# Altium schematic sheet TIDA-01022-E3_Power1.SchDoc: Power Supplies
size 431 x 279 mm; Date: Not shown in title block; ApprovedBy: Not shown in title block; CheckedBy: Not shown in title block; Author: Not shown in title block; CompanyName: Not shown in title block; DrawnBy: Avinash N; Engineer: Not shown in title block; Organization: Not shown in title block; Address1: Not shown in title block; Address2: Not shown in title block; Address3: Not shown in title block; Address4: Not shown in title block; DocumentNumber: 1; Revision: Use project parameter SCH_Rev; SheetNumber: 21; SheetTotal: 26; PageSetup: Record=PageOptions¦CenterHorizontal=True¦CenterVertical=True¦PrintScale=1.00¦XCorrection=1.00¦YCorrection=1.00¦PrintKind=0¦BorderSize=5000000¦LeftOffset=0¦BottomOffset=0¦Orientation=2¦PaperLength=1000¦PaperWidth=1000¦Scale=100¦PaperSource=15¦PrintQuality=600¦MediaType=1¦DitherType=10¦PaperKind=Letter¦PrintScaleMode=1
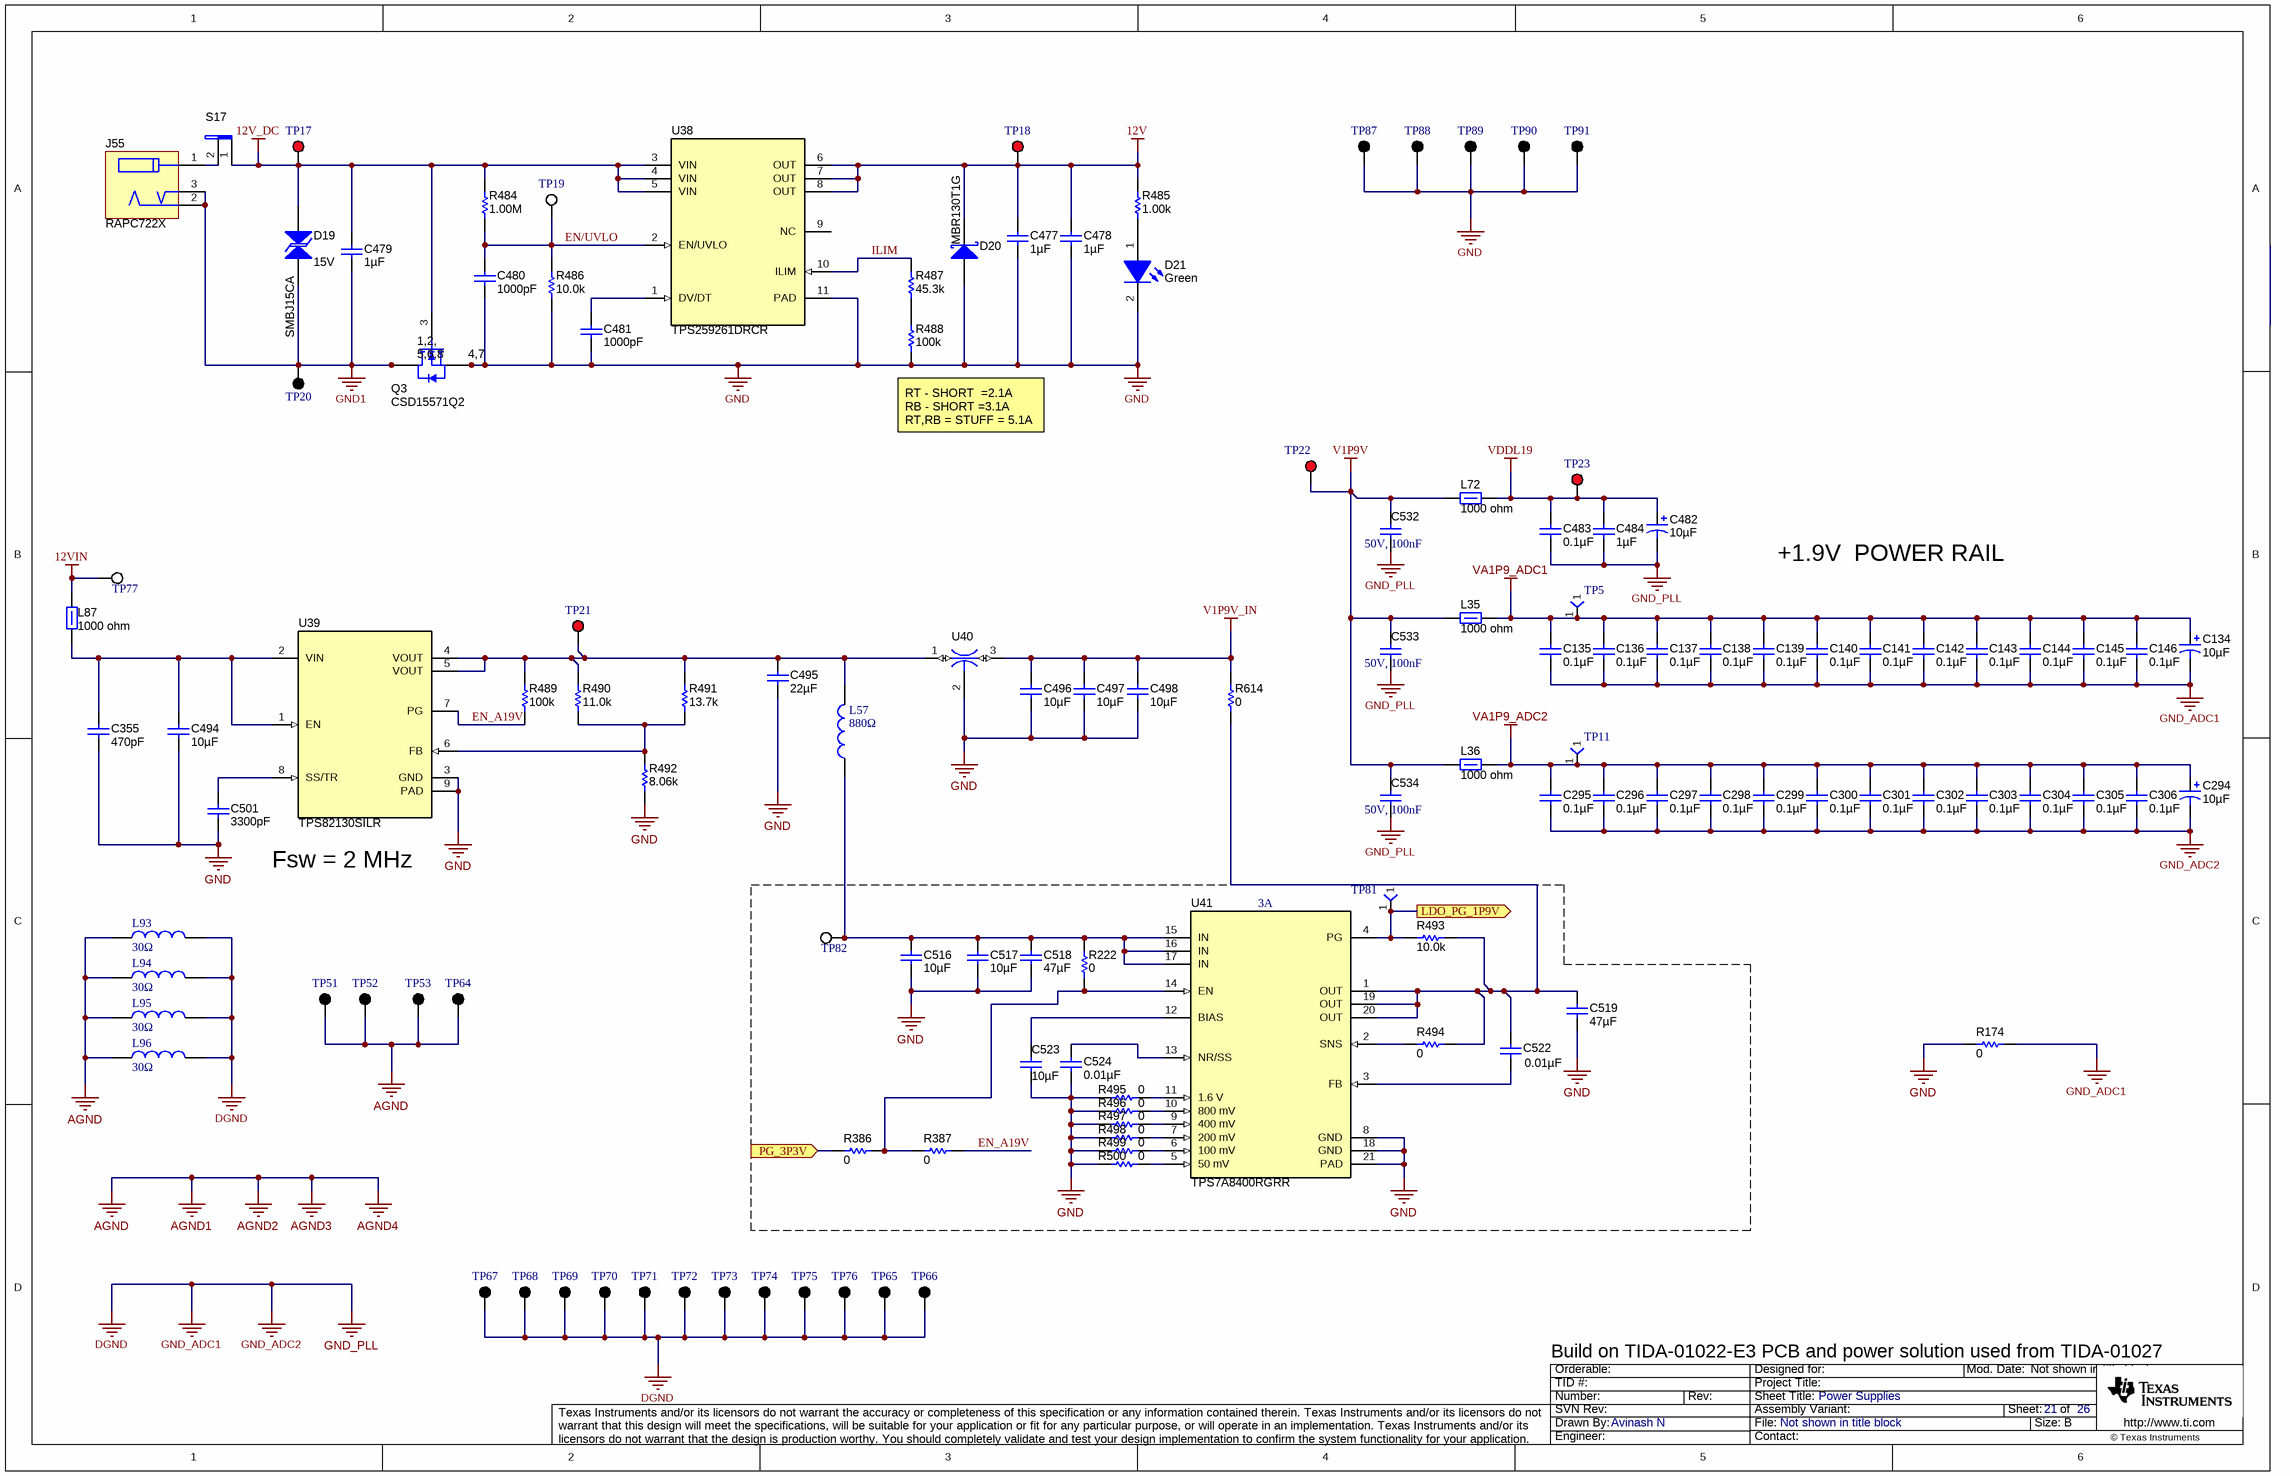
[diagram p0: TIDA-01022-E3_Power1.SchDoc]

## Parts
C134  ValueDisplayed: 10µF  [3528-21]  (hidden comment: 293D106X0010B2TE3)
C135  ValueDisplayed: 0.1µF  [0201]  (hidden comment: GRM033C71A104KE14D)
C136  ValueDisplayed: 0.1µF  [0201]  (hidden comment: GRM033C71A104KE14D)
C137  ValueDisplayed: 0.1µF  [0201]  (hidden comment: GRM033C71A104KE14D)
C138  ValueDisplayed: 0.1µF  [0201]  (hidden comment: GRM033C71A104KE14D)
C139  ValueDisplayed: 0.1µF  [0201]  (hidden comment: GRM033C71A104KE14D)
C140  ValueDisplayed: 0.1µF  [0201]  (hidden comment: GRM033C71A104KE14D)
C141  ValueDisplayed: 0.1µF  [0201]  (hidden comment: GRM033C71A104KE14D)
C142  ValueDisplayed: 0.1µF  [0201]  (hidden comment: GRM033C71A104KE14D)
C143  ValueDisplayed: 0.1µF  [0201]  (hidden comment: GRM033C71A104KE14D)
C144  ValueDisplayed: 0.1µF  [0201]  (hidden comment: GRM033C71A104KE14D)
C145  ValueDisplayed: 0.1µF  [0201]  (hidden comment: GRM033C71A104KE14D)
C146  ValueDisplayed: 0.1µF  [0201]  (hidden comment: GRM033C71A104KE14D)
C294  ValueDisplayed: 10µF  [3528-21]  (hidden comment: 293D106X0010B2TE3)
C295  ValueDisplayed: 0.1µF  [0201]  (hidden comment: GRM033C71A104KE14D)
C296  ValueDisplayed: 0.1µF  [0201]  (hidden comment: GRM033C71A104KE14D)
C297  ValueDisplayed: 0.1µF  [0201]  (hidden comment: GRM033C71A104KE14D)
C298  ValueDisplayed: 0.1µF  [0201]  (hidden comment: GRM033C71A104KE14D)
C299  ValueDisplayed: 0.1µF  [0201]  (hidden comment: GRM033C71A104KE14D)
C300  ValueDisplayed: 0.1µF  [0201]  (hidden comment: GRM033C71A104KE14D)
C301  ValueDisplayed: 0.1µF  [0201]  (hidden comment: GRM033C71A104KE14D)
C302  ValueDisplayed: 0.1µF  [0201]  (hidden comment: GRM033C71A104KE14D)
C303  ValueDisplayed: 0.1µF  [0201]  (hidden comment: GRM033C71A104KE14D)
C304  ValueDisplayed: 0.1µF  [0201]  (hidden comment: GRM033C71A104KE14D)
C305  ValueDisplayed: 0.1µF  [0201]  (hidden comment: GRM033C71A104KE14D)
C306  ValueDisplayed: 0.1µF  [0201]  (hidden comment: GRM033C71A104KE14D)
C355  ValueDisplayed: 470pF  [0402]  (hidden comment: GRM1555C1H471JA01D)
C477  ValueDisplayed: 1µF  [0805_HV]  (hidden comment: 08053D105KAT2A)
C478  ValueDisplayed: 1µF  [0805_HV]  (hidden comment: 08053D105KAT2A)
C479  ValueDisplayed: 1µF  [0805_HV]  (hidden comment: 08053D105KAT2A)
C480  ValueDisplayed: 1000pF  [0603]  (hidden comment: 06031C102MAT2A)
C481  ValueDisplayed: 1000pF  [0603]  (hidden comment: 06031C102MAT2A)
C482  ValueDisplayed: 10µF  [3528-21]  (hidden comment: 293D106X0010B2TE3)
C483  ValueDisplayed: 0.1µF  [0201]  (hidden comment: GRM033C71A104KE14D)
C484  ValueDisplayed: 1µF  [0603]  (hidden comment: C1608X5R1A105K080AC)
C494  ValueDisplayed: 10µF  [1206_190]  (hidden comment: C3216X7R1E106M160AE)
C495  ValueDisplayed: 22µF  [0805_HV]  (hidden comment: JMK212BJ226MG-T)
C496  ValueDisplayed: 10µF  [1206_190]  (hidden comment: C3216X7R1E106M160AE)
C497  ValueDisplayed: 10µF  [1206_190]  (hidden comment: C3216X7R1E106M160AE)
C498  ValueDisplayed: 10µF  [1206_190]  (hidden comment: C3216X7R1E106M160AE)
C501  ValueDisplayed: 3300pF  [0603]  (hidden comment: GRM1885C1H332JA01D)
C516  ValueDisplayed: 10µF  [0805_HV]  (hidden comment: GRM21BR61C106KE15L)
C517  ValueDisplayed: 10µF  [0805_HV]  (hidden comment: GRM21BR61C106KE15L)
C518  ValueDisplayed: 47µF  [0805_HV]  (hidden comment: GRM219R60G476ME44D)
C519  ValueDisplayed: 47µF  [0805_HV]  (hidden comment: GRM219R60G476ME44D)
C522  ValueDisplayed: 0.01µF  [0603]  (hidden comment: GRM188R71H103KA01D)
C523  ValueDisplayed: 10µF  [0805_HV]  (hidden comment: GRM21BR61C106KE15L)
C524  ValueDisplayed: 0.01µF  [0603]  (hidden comment: GRM188R71H103KA01D)
C532  50V, 100nF  [0603_1.6x0.8x0.8mm_Reflow Soldering]
C533  50V, 100nF  [0603_1.6x0.8x0.8mm_Reflow Soldering]
C534  50V, 100nF  [0603_1.6x0.8x0.8mm_Reflow Soldering]
D19  SMBJ15CA  value 15V  [SMB-Bi]
D20  MBR130T1G  [SOD-123]
D21  value Green  [LTST-C191_Green]  (hidden comment: LTST-C191TGKT)
J55  RAPC722X  [CONN_RAPC722X]
L35  ValueDisplayed: 1000 ohm  [1806_HighSpeed]  (hidden comment: BLM41PG102SN1L)
L36  ValueDisplayed: 1000 ohm  [1806_HighSpeed]  (hidden comment: BLM41PG102SN1L)
L57  880Ω  [WE-CBF_1812_High Current]
L72  ValueDisplayed: 1000 ohm  [1806_HighSpeed]  (hidden comment: BLM41PG102SN1L)
L87  ValueDisplayed: 1000 ohm  [1806_HighSpeed]  (hidden comment: BLM41PG102SN1L)
L93  30Ω  [WE-CBF_1210_High Current]
L94  30Ω  [WE-CBF_1210_High Current]
L95  30Ω  [WE-CBF_1210_High Current]
L96  30Ω  [WE-CBF_1210_High Current]
Q3  CSD15571Q2  [DQK0006C]
R174  ValueDisplayed: 0  [1206]  (hidden comment: CRCW12060000Z0EA)
R222  ValueDisplayed: 0  [0603]  (hidden comment: CRCW06030000Z0EA)
R386  ValueDisplayed: 0  [0603]  (hidden comment: CRCW06030000Z0EA)
R387  ValueDisplayed: 0  [0603]  (hidden comment: CRCW06030000Z0EA)
R484  ValueDisplayed: 1.00M  [0603]  (hidden comment: CRCW06031M00FKEA)
R485  ValueDisplayed: 1.00k  [0603]  (hidden comment: CRCW06031K00FKEA)
R486  ValueDisplayed: 10.0k  [0603]  (hidden comment: CRCW060310K0FKEA)
R487  ValueDisplayed: 45.3k  [0603]  (hidden comment: CRCW060345K3FKEA)
R488  ValueDisplayed: 100k  [0603]  (hidden comment: CRCW0603100KFKEA)
R489  ValueDisplayed: 100k  [0402]  (hidden comment: CRCW0402100KFKED)
R490  ValueDisplayed: 11.0k  [0402]  (hidden comment: CRCW040211K0FKED)
R491  ValueDisplayed: 13.7k  [0402]  (hidden comment: CRCW040213K7FKED)
R492  ValueDisplayed: 8.06k  [0402]  (hidden comment: CRCW04028K06FKED)
R493  ValueDisplayed: 10.0k  [0603]  (hidden comment: CRCW060310K0FKEA)
R494  ValueDisplayed: 0  [0603]  (hidden comment: CRCW06030000Z0EA)
R495  ValueDisplayed: 0  [0402]  (hidden comment: CRCW04020000Z0ED)
R496  ValueDisplayed: 0  [0402]  (hidden comment: CRCW04020000Z0ED)
R497  ValueDisplayed: 0  [0402]  (hidden comment: CRCW04020000Z0ED)
R498  ValueDisplayed: 0  [0402]  (hidden comment: CRCW04020000Z0ED)
R499  ValueDisplayed: 0  [0402]  (hidden comment: CRCW04020000Z0ED)
R500  ValueDisplayed: 0  [0402]  (hidden comment: CRCW04020000Z0ED)
R614  ValueDisplayed: 0  [1206]  (hidden comment: CRCW12060000Z0EA)
S17  L101011MS02Q  [SW_ L101011MS02Q]  (value not drawn)
TP5  TP-025-SMT  [PROBE_POINT_30PAD]  (value not drawn)
TP11  TP-025-SMT  [PROBE_POINT_30PAD]  (value not drawn)
TP17  5000  [Keystone5000]  (value not drawn)
TP18  5000  [Keystone5000]  (value not drawn)
TP19  5012  [Keystone5012]  (value not drawn)
TP20  5001  [Keystone5001]  (value not drawn)
TP21  5000  [Keystone5000]  (value not drawn)
TP22  5000  [Keystone5000]  (value not drawn)
TP23  5000  [Keystone5000]  (value not drawn)
TP51  5001  [Keystone5001]  (value not drawn)
TP52  5001  [Keystone5001]  (value not drawn)
TP53  5001  [Keystone5001]  (value not drawn)
TP64  5001  [Keystone5001]  (value not drawn)
TP65  5001  [Keystone5001]  (value not drawn)
TP66  5001  [Keystone5001]  (value not drawn)
TP67  5001  [Keystone5001]  (value not drawn)
TP68  5001  [Keystone5001]  (value not drawn)
TP69  5001  [Keystone5001]  (value not drawn)
TP70  5001  [Keystone5001]  (value not drawn)
TP71  5001  [Keystone5001]  (value not drawn)
TP72  5001  [Keystone5001]  (value not drawn)
TP73  5001  [Keystone5001]  (value not drawn)
TP74  5001  [Keystone5001]  (value not drawn)
TP75  5001  [Keystone5001]  (value not drawn)
TP76  5001  [Keystone5001]  (value not drawn)
TP77  5015  [Testpoint_Keystone_Miniature]  (value not drawn)
TP81  TP-025-SMT  [PROBE_POINT_30PAD]  (value not drawn)
TP82  5015  [Testpoint_Keystone_Miniature]  (value not drawn)
TP87  5001  [Keystone5001]  (value not drawn)
TP88  5001  [Keystone5001]  (value not drawn)
TP89  5001  [Keystone5001]  (value not drawn)
TP90  5001  [Keystone5001]  (value not drawn)
TP91  5001  [Keystone5001]  (value not drawn)
U38  TPS259261DRCR  [DRC0010J]
U39  TPS82130SILR  [SIL0008D_SMD]
U40  NFM31PC276B0J3L  [Murata_NFM31P]  (value not drawn)
U41  TPS7A8400RGRR  [RGR0020A]

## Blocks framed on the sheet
3A: C516-C519 C522-C524 R222 R386 R387 R493-R500 TP81 TP82 U41

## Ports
LDO_PG_1P9V (out), PG_3P3V (in)

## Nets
12V: C477.1 C478.1 D20.1(K) R485.2 TP18.1 U38.6(OUT) U38.7(OUT) U38.8(OUT)
12V_DC: C479.1 D19.2 Q3.3(G) R484.2 S17.1 TP17.1 U38.3(VIN) U38.4(VIN) U38.5(VIN)
12VIN: L87.2 TP77.1
AGND: L93.1 L94.1 L95.1 L96.1 TP51.1 TP52.1 TP53.1 TP64.1  [also labelled AGND1, AGND2, AGND3, AGND4]
DGND: C134.2(-) C135.2 C136.2 C137.2 C138.2 C139.2 C140.2 C141.2 C142.2 C143.2 C144.2 C145.2 C146.2 C294.2(-) C295.2 C296.2 C297.2 C298.2 C299.2 C300.2 C301.2 C302.2 C303.2 C304.2 C305.2 C306.2 C482.2(-) C483.2 C484.2 C532.1 C533.1 C534.1 L93.2 L94.2 L95.2 L96.2 R174.2 TP65.1 TP66.1 TP67.1 TP68.1 TP69.1 TP70.1 TP71.1 TP72.1 TP73.1 TP74.1 TP75.1 TP76.1  [also labelled GND_ADC1, GND_ADC2, GND_PLL]
GND: C355.2 C477.2 C478.2 C480.2 C481.2 C494.2 C495.2 C496.1 C497.1 C498.1 C501.1 C516.2 C517.2 C518.2 C519.2 C523.2 C524.2 D20.2(A) D21.2(K) Q3.4(S) Q3.7(S) R174.1 R486.1 R488.1 R492.1 R495.1 R496.1 R497.1 R498.1 R499.1 R500.1 TP87.1 TP88.1 TP89.1 TP90.1 TP91.1 U38.11(PAD) U39.3(GND) U39.9(PAD) U40.2 U41.8(GND) U41.18(GND) U41.21(PAD)
GND1: C479.2 D19.1 J55.2 J55.3 Q3.1(D) Q3.2(D) Q3.5(D) Q3.6(D) Q3.8(D) TP20.1
V1P9V: C532.2 C533.2 C534.2 L35.1 L36.1 L72.1 TP22.1
V1P9V_IN: C496.2 C497.2 C498.2 R614.2 U40.3
VA1P9_ADC1: C134.1(+) C135.1 C136.1 C137.1 C138.1 C139.1 C140.1 C141.1 C142.1 C143.1 C144.1 C145.1 C146.1 L35.2 TP5.1
VA1P9_ADC2: C294.1(+) C295.1 C296.1 C297.1 C298.1 C299.1 C300.1 C301.1 C302.1 C303.1 C304.1 C305.1 C306.1 L36.2 TP11.1
VDDL19: C482.1(+) C483.1 C484.1 L72.2 TP23.1
EN/UVLO: C480.1 R484.1 R486.2 TP19.1 U38.2(EN/UVLO)
EN_A19V: R387.1 R489.1 U39.7(PG)
ILIM: R487.2 U38.10(ILIM)
LDO_PG_1P9V: R493.2 TP81.1 U41.4(PG) ; port LDO_PG_1P9V
PG_3P3V: R386.2 ; port PG_3P3V
NetC355_1: C355.1 C494.1 L87.1 U39.1(EN) U39.2(VIN)
NetC481_1: C481.1 U38.1(DV/DT)
NetC495_1: C495.1 L57.2 R489.2 R490.2 R491.2 TP21.1 U39.4(VOUT) U39.5(VOUT) U40.1
NetC501_2: C501.2 U39.8(SS/TR)
NetC516_1: C516.1 C517.1 C518.1 L57.1 R222.1 TP82.1 U41.15(IN) U41.16(IN) U41.17(IN)
NetC519_1: C519.1 C522.1 R493.1 R494.2 R614.1 U41.1(OUT) U41.19(OUT) U41.20(OUT)
NetC522_2: C522.2 U41.3(FB)
NetC523_1: C523.1 U41.12(BIAS)
NetC524_1: C524.1 U41.13(NR/SS)
NetD21_1: D21.1(A) R485.1
NetJ55_1: J55.1 S17.2
NetR222_2: R222.2 R386.1 R387.2 U41.14(EN)
NetR487_1: R487.1 R488.2
NetR490_1: R490.1 R491.1 R492.2 U39.6(FB)
NetR494_1: R494.1 U41.2(SNS)
NetR495_2: R495.2 U41.11(1.6_V)
NetR496_2: R496.2 U41.10(800_mV)
NetR497_2: R497.2 U41.9(400_mV)
NetR498_2: R498.2 U41.7(200_mV)
NetR499_2: R499.2 U41.6(100_mV)
NetR500_2: R500.2 U41.5(50_mV)

Not connected (* = marked no-connect by the designer): U38 9(NC)

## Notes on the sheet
- (near R488) RT - SHORT  =2.1A
  RB - SHORT =3.1A
  RT,RB = STUFF = 5.1A
- +1.9V  POWER RAIL
- Fsw = 2 MHz
- Build on TIDA-01022-E3 PCB and power solution used from TIDA-01027

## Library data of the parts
C134 C294 C482 = 293D106X0010B2TE3: CAP, TA, 10 µF, 10 V, +/- 20%, 2.5 ohm, SMD; Manufacturer: Vishay-Sprague; Polarized: Y; CompType: Capacitor; Value: 10uF; U/M: EA; Cap_F: 0.00001; Tolerance_%: 20; Value1: 2.5 ohm; VDC_V: 10; Value2: 10V; ESR_ohm: 2.5; IRMS_A: 0.18; TaMin_C: -55; TaMax_C: 125; Cap_Case: B; SizeAreaWB_mm2: 17.1; SizeArea_mm2: 9.8; SizeX_mm: 3.5; SizeY_mm: 2.8; SizeZ_mm: 2.1; AEC Category: Q200
C135-C146 C295-C306 C483 = GRM033C71A104KE14D: CAP, CERM, 0.1 µF, 10 V, +/- 10%, X7S, 0201; Manufacturer: MuRata; Polarized: N; CompType: Capacitor; Value: 0.1uF; U/M: EA; Cap_F: 0.0000001; Tolerance_%: 10; Value1: Unknown; Value2: 10V; TaMin_C: -55; TaMax_C: 125; SizeArea_mm2: 0.18; SizeAreaWB_mm2: 2.08; SizeX_mm: 0.6; SizeY_mm: 0.3; SizeZ_mm: 0.26; AEC Category: Q200
C355 = GRM1555C1H471JA01D: CAP, CERM, 470 pF, 50 V, +/- 5%, C0G/NP0, 0402; Manufacturer: MuRata; Polarized: N; CompType: Capacitor; Value: 470pF; U/M: EA; Cap_F: 0.00000000047; Tolerance_%: 5; Value1: Unknown; VDC_V: 50; Value2: 50V; TaMin_C: -55; TaMax_C: 125; SizeArea_mm2: 0.5; SizeAreaWB_mm2: 3; SizeX_mm: 1; SizeZ_mm: 0.6; AEC Category: Q200
C477-C479 = 08053D105KAT2A: CAP, CERM, 1 µF, 25 V, +/- 10%, X5R, 0805; Manufacturer: AVX; Polarized: N; CompType: Capacitor; Value: 1uF; U/M: EA; Cap_F: 0.000001; Tolerance_%: 10; ESR_ohm: 0.012; Value1: 0.012 ohm; VDC_V: 25; Value2: 25V; TaMin_C: -55; TaMax_C: 85; Cap_Case: 0805; SizeArea_mm2: 2.5; SizeAreaWB_mm2: 6.75; SizeX_mm: 2; SizeY_mm: 1.25; SizeZ_mm: 1.45; AEC Category: Q200
C480 C481 = 06031C102MAT2A: CAP, CERM, 1000 pF, 100 V, +/- 20%, X7R, 0603; Manufacturer: AVX; Polarized: N; CompType: Capacitor; Value: 1000pF; U/M: EA; Cap_F: 0.000000001; Tolerance_%: 20; ESR_ohm: 0.276; Value1: 0.276 ohm; VDC_V: 100; Value2: 100V; TaMin_C: -55; TaMax_C: 125; SizeArea_mm2: 1.28; SizeAreaWB_mm2: 4.68; SizeX_mm: 1.6; SizeY_mm: 0.8; SizeZ_mm: 1; AEC Category: Q200
C484 = C1608X5R1A105K080AC: CAP, CERM, 1 µF, 10 V, +/- 10%, X5R, 0603; Manufacturer: TDK; Polarized: N; CompType: Capacitor; Value: 1uF; U/M: EA; Cap_F: 0.000001; Tolerance_%: 10; Value1: Unknown; Value2: 10V; TaMin_C: -55; TaMax_C: 85; SizeArea_mm2: 1.28; SizeAreaWB_mm2: 4.68; SizeX_mm: 1.6; SizeY_mm: 0.8; SizeZ_mm: 1; AEC Category: Q200
C494 C496-C498 = C3216X7R1E106M160AE: CAP, CERM, 10 µF, 25 V, +/- 20%, X7R, 1206_190; Manufacturer: TDK; Polarized: N; CompType: Capacitor; Value: 10uF; U/M: EA; Cap_F: 0.00001; Tolerance_%: 20; Value1: Unknown; VDC_V: 25; Value2: 25V; TaMin_C: -55; TaMax_C: 125; Cap_Case: 1206; SizeArea_mm2: 5.12; SizeAreaWB_mm2: 10.92; SizeX_mm: 3.2; SizeY_mm: 1.6; SizeZ_mm: 1.9; AEC Category: Q200
C495 = JMK212BJ226MG-T: CAP, CERM, 22 µF, 6.3 V, +/- 20%, X5R, 0805; Manufacturer: Taiyo Yuden; Polarized: N; CompType: Capacitor; Value: 22uF; U/M: EA; Cap_F: 0.000022; Tolerance_%: 20; Value1: Unknown; VDC_V: 6.3; Value2: 6.3V; TaMin_C: -55; TaMax_C: 85; Cap_Case: 0805; SizeArea_mm2: 2.5; SizeAreaWB_mm2: 6.75; SizeX_mm: 2; SizeY_mm: 1.25; SizeZ_mm: 1.45; AEC Category: Q200
C501 = GRM1885C1H332JA01D: CAP, CERM, 3300 pF, 50 V, +/- 5%, C0G/NP0, 0603; Manufacturer: MuRata; Polarized: N; CompType: Capacitor; Value: 3300pF; U/M: EA; Cap_F: 0.0000000033; Tolerance_%: 5; Value1: Unknown; VDC_V: 50; Value2: 50V; TaMin_C: -55; TaMax_C: 125; SizeArea_mm2: 1.28; SizeAreaWB_mm2: 4.68; SizeX_mm: 1.6; SizeY_mm: 0.8; SizeZ_mm: 1; AEC Category: Q200
C516 C517 C523 = GRM21BR61C106KE15L: CAP, CERM, 10 µF, 16 V, +/- 10%, X5R, 0805; Manufacturer: MuRata; Polarized: N; CompType: Capacitor; Value: 10uF; U/M: EA; Cap_F: 0.00001; Tolerance_%: 10; ESR_ohm: 0.008; Value1: 0.008 ohm; VDC_V: 16; Value2: 16V; TaMin_C: -55; TaMax_C: 85; Cap_Case: 0805; SizeArea_mm2: 2.5; SizeAreaWB_mm2: 6.75; SizeX_mm: 2; SizeY_mm: 1.25; SizeZ_mm: 1.45; AEC Category: Q200
C518 C519 = GRM219R60G476ME44D: CAP, CERM, 47 µF, 4 V, +/- 20%, X5R, 0805; Manufacturer: MuRata; Polarized: N; CompType: Capacitor; Value: 47uF; U/M: EA; Cap_F: 0.000047; Tolerance_%: 20; Value1: Unknown; VDC_V: 4; Value2: 4V; TaMin_C: -55; TaMax_C: 85; Cap_Case: 0805; SizeArea_mm2: 2.5; SizeAreaWB_mm2: 6.75; SizeX_mm: 2; SizeY_mm: 1.25; SizeZ_mm: 1.45; AEC Category: Q200
C522 C524 = GRM188R71H103KA01D: CAP, CERM, 0.01 µF, 50 V, +/- 10%, X7R, 0603; Manufacturer: MuRata; Polarized: N; CompType: Capacitor; Value: 0.01uF; U/M: EA; Cap_F: 0.00000001; Tolerance_%: 10; Value1: Unknown; VDC_V: 50; Value2: 50V; TaMin_C: -55; TaMax_C: 125; SizeArea_mm2: 1.28; SizeAreaWB_mm2: 4.68; SizeX_mm: 1.6; SizeY_mm: 0.8; SizeZ_mm: 1; AEC Category: Q200
C532-C534 = 885012206095: WCAP-CSGP Ceramic Capacitors, 0603, X7R, 50V, 100nF; Rated Voltage: 50V DC
D19 = SMBJ15CA: Diode, TVS, Bi, 15 V, 24.4 Vc, SMB; Manufacturer: Fairchild Semiconductor; U/M: EA; Vr_V: 15; Value1: W; AEC Category: Q101
D20 = MBR130T1G: Diode, Schottky, 30 V, 1 A, SOD-123; Manufacturer: ON Semiconductor; U/M: EA; Vf_V: 0.47; Value: 30V; Value1: 1A; Value2: 0.47V; Io_A: 1; Vr_V: 30; TJmax_C: 125; RJC_CperW: 108; SizeAreaWB_mm2: 13.095; SizeArea_mm2: 6.545; SizeX_mm: 3.85; SizeY_mm: 1.7; SizeZ_mm: 1.35; AEC Category: Q101
D21 = LTST-C191TGKT: LED, Green, SMD; Manufacturer: Lite-On; Type: InGaN; Vf_V: 3.2; Value2: 3.2V; Io_A: 0.02; Value1: W; U/M: EA
J55 = RAPC722X: Power Jack, mini, 2.1mm OD, R/A, TH; Manufacturer: Switchcraft; SymbolCreator: a0799628
L35 L36 L72 L87 = BLM41PG102SN1L: Ferrite Bead, 1000 ohm @ 100 MHz, 1.5 A, 1806; Manufacturer: MuRata; Imax_A: 1.5; DCR_ohm: 0.09; Value1: 0.09 ohm; Value2: 1.5A; SizeAreaWB_mm2: 14.3; SizeArea_mm2: 7.2; SizeX_mm: 4.5; SizeY_mm: 1.6; SizeZ_mm: 1.85; ZTyp@100MHz_Ohm: 1000
L57 = WE-CBF, 74279252: WE-CBF SMD EMI Suppression Ferrite Bead, 1812, 880Ω; Type: High Current
L93-L96 = WE-CBF, 742792310: WE-CBF SMD EMI Suppression Ferrite Bead, 1210, 30Ω; Type: High Current
Q3 = CSD15571Q2: MOSFET, N-CH, 20 V, 10 A, DQK0006C (WSON-6); Manufacturer: Texas Instruments; Alternate Manufacturer: None; U/M: EA; ChType: N; Value: 20V; VdsMax_V: 20; Value1: 19.2 ohm; Rdson45_ohm: 19.2; Value2: 2.5 nC; QgTyp_nC: 2.5; IdsMax_A: 10; SizeAreaWB_mm2: 9; SizeArea_mm2: 4; SizeX_mm: 2; SizeZ_mm: 0.8; AEC Category: Q101
R174 = CRCW12060000Z0EA: RES, 0, 5%, 0.25 W, 1206; Manufacturer: Vishay-Dale; CompType: Resistor; Value: 0; Value_Code: 0000; Tolerance_%: 5; Power_W: 0.25; Value2: 0.25W; VDC_V: 200; TempCo: 200 ppm/C; SizeArea_mm2: 5.12; SizeX_mm: 3.2; SizeY_mm: 1.6; SizeZ_mm: 1.35; EIA_Code: E24; U/M: EA; AEC Category: Q200; Green_Lifecycle: Active; Green_REACh: Passed
R222 R386 R387 = CRCW06030000Z0EA: RES, 0, 5%, 0.1 W, 0603; Manufacturer: Vishay-Dale; CompType: Resistor; Value: 0; Value_Code: 0000; Tolerance_%: 5; Power_W: 0.1; Value2: 0.1W; VDC_V: 75; TempCo: 200 ppm/C; SizeArea_mm2: 1.28; SizeX_mm: 1.6; SizeY_mm: 0.8; SizeZ_mm: 1; EIA_Code: E24; U/M: EA; AEC Category: Q200; Green_Lifecycle: Active; Green_REACh: Passed
R484 = CRCW06031M00FKEA: RES, 1.00 M, 1%, 0.1 W, 0603; Manufacturer: Vishay-Dale; CompType: Resistor; Value: 1.00Meg; Res_ohm: 1000000; Value_Code: 1M00; Tolerance_%: 1; Power_W: 0.1; Value2: 0.1W; VDC_V: 75; TempCo: 100 ppm/C; SizeArea_mm2: 1.28; SizeX_mm: 1.6; SizeY_mm: 0.8; EIA_Code: E96; U/M: EA; AEC Category: Q200
R485 = CRCW06031K00FKEA: RES, 1.00 k, 1%, 0.1 W, 0603; Manufacturer: Vishay-Dale; CompType: Resistor; Value: 1.00k; Res_ohm: 1000; Value_Code: 1k00; Tolerance_%: 1; Power_W: 0.1; Value2: 0.1W; VDC_V: 75; TempCo: 100 ppm/C; SizeArea_mm2: 1.28; SizeX_mm: 1.6; SizeY_mm: 0.8; EIA_Code: E96; U/M: EA; AEC Category: Q200
R486 R493 = CRCW060310K0FKEA: RES, 10.0 k, 1%, 0.1 W, 0603; Manufacturer: Vishay-Dale; CompType: Resistor; Value: 10.0k; Res_ohm: 10000; Value_Code: 10k0; Tolerance_%: 1; Power_W: 0.1; Value2: 0.1W; VDC_V: 75; TempCo: 100 ppm/C; SizeArea_mm2: 1.28; SizeX_mm: 1.6; SizeY_mm: 0.8; EIA_Code: E96; U/M: EA; AEC Category: Q200
R487 = CRCW060345K3FKEA: RES, 45.3 k, 1%, 0.1 W, 0603; Manufacturer: Vishay-Dale; CompType: Resistor; Value: 45.3k; Res_ohm: 45300; Value_Code: 45k3; Tolerance_%: 1; Power_W: 0.1; Value2: 0.1W; VDC_V: 75; TempCo: 100 ppm/C; SizeArea_mm2: 1.28; SizeX_mm: 1.6; SizeY_mm: 0.8; EIA_Code: E96; U/M: EA; AEC Category: Q200
R488 = CRCW0603100KFKEA: RES, 100 k, 1%, 0.1 W, 0603; Manufacturer: Vishay-Dale; CompType: Resistor; Value: 100k; Res_ohm: 100000; Tolerance_%: 1; Power_W: 0.1; Value2: 0.1W; VDC_V: 75; TempCo: 100 ppm/C; SizeArea_mm2: 1.28; SizeX_mm: 1.6; SizeY_mm: 0.8; EIA_Code: E96; U/M: EA; AEC Category: Q200
R489 = CRCW0402100KFKED: RES, 100 k, 1%, 0.063 W, 0402; Manufacturer: Vishay-Dale; CompType: Resistor; Value: 100k; Res_ohm: 100000; Tolerance_%: 1; Power_W: 0.063; Value2: 0.063W; VDC_V: 50; TempCo: 100 ppm/C; SizeArea_mm2: 0.5; SizeZ_mm: 0.6; EIA_Code: E96; U/M: EA; AEC Category: Q200
R490 = CRCW040211K0FKED: RES, 11.0 k, 1%, 0.063 W, 0402; Manufacturer: Vishay-Dale; CompType: Resistor; Value: 11.0k; Res_ohm: 11000; Value_Code: 11k0; Tolerance_%: 1; Power_W: 0.063; Value2: 0.063W; VDC_V: 50; TempCo: 100 ppm/C; SizeArea_mm2: 0.5; SizeZ_mm: 0.6; EIA_Code: E96; U/M: EA; AEC Category: Q200
R491 = CRCW040213K7FKED: RES, 13.7 k, 1%, 0.063 W, 0402; Manufacturer: Vishay-Dale; CompType: Resistor; Value: 13.7k; Res_ohm: 13700; Value_Code: 13k7; Tolerance_%: 1; Power_W: 0.063; Value2: 0.063W; VDC_V: 50; TempCo: 100 ppm/C; SizeArea_mm2: 0.5; SizeZ_mm: 0.6; EIA_Code: E96; U/M: EA; AEC Category: Q200
R492 = CRCW04028K06FKED: RES, 8.06 k, 1%, 0.063 W, 0402; Manufacturer: Vishay-Dale; CompType: Resistor; Value: 8.06k; Res_ohm: 8060; Value_Code: 8k06; Tolerance_%: 1; Power_W: 0.063; Value2: 0.063W; VDC_V: 50; TempCo: 100 ppm/C; SizeArea_mm2: 0.5; SizeZ_mm: 0.6; EIA_Code: E96; U/M: EA; AEC Category: Q200
R494 = CRCW06030000Z0EA: RES, 0, 5%, 0.1 W, 0603; Manufacturer: Vishay-Dale; CompType: Resistor; Value: 0; Value_Code: 0000; Tolerance_%: 5; Power_W: 0.1; Value2: 0.1W; VDC_V: 75; TempCo: 200 ppm/C; SizeArea_mm2: 1.28; SizeX_mm: 1.6; SizeY_mm: 0.8; SizeZ_mm: 1; EIA_Code: E24; U/M: EA; AEC Category: Q200
R495-R500 = CRCW04020000Z0ED: RES, 0, 5%, 0.063 W, 0402; Manufacturer: Vishay-Dale; CompType: Resistor; Value: 0; Value_Code: 0000; Tolerance_%: 5; Power_W: 0.063; Value2: 0.063W; VDC_V: 50; TempCo: 200 ppm/C; SizeArea_mm2: 0.5; SizeX_mm: 1; SizeZ_mm: 0.6; EIA_Code: E24; U/M: EA; AEC Category: Q200
R614 = CRCW12060000Z0EA: RES, 0, 5%, 0.25 W, 1206; Manufacturer: Vishay-Dale; CompType: Resistor; Value: 0; Value_Code: 0000; Tolerance_%: 5; Power_W: 0.25; Value2: 0.25W; VDC_V: 200; TempCo: 200 ppm/C; SizeArea_mm2: 5.12; SizeX_mm: 3.2; SizeY_mm: 1.6; SizeZ_mm: 1.35; EIA_Code: E24; U/M: EA; AEC Category: Q200
S17 = L101011MS02Q: SWITCH SLIDE SPST 4A PCB, TH; Manufacturer: C&K Components; Symbol Creator: a0411947; VDC_V: 125; SwitchFunction: Off-On; PositionCount: 1; CurrentRating_mA: 4000
TP5 TP11 TP81 = TP-025-SMT: Test Point, O.025"; Manufacturer: STD; Value: STD
TP17 TP18 TP21 TP22 = 5000: Test Point, Miniature, Red, TH; Manufacturer: Keystone; CompType: Test Point Loop; ContactFinish: Silver; Green_Lifecycle: Active; Green_REACh: Passed
TP19 = 5012: Test Point, Multipurpose, White, TH; Manufacturer: Keystone; CompType: Test Point Loop; ContactFinish: Silver
TP20 TP51-TP53 TP64-TP76 TP87-TP91 = 5001: Test Point, Miniature, Black, TH; Manufacturer: Keystone; CompType: Test Point Loop; ContactFinish: Silver; Green_Lifecycle: Active; Green_REACh: Passed
TP23 = 5000: Test Point, Miniature, Red, TH; Manufacturer: Keystone; CompType: Test Point Loop; ContactFinish: Silver
TP77 TP82 = 5015: Test Point, Miniature, SMT; Manufacturer: Keystone; CompType: Test Point Loop; Green_Lifecycle: Active; Green_REACh: Passed
U38 = TPS259261DRCR: 12V, 5A, 30mΩ eFuse with Adjustable +/-15% Accurate Current Limit, DRC0010J (VSON-10); Alternate PartNumber: TPS259261DRCT; Manufacturer: Texas Instruments; SymbolCreator: Altium; SizeArea_mm2: 9; SizeAreaWB_mm2: 16; SizeX_mm: 3; SizeZ_mm: 1; CompType: IC; U/M: EA
U39 = TPS82130SILR: 3-A 17V Step-down Converter Module with Integrated Inductor, SIL0008D (uSIP-8); Alternate PartNumber: TPS82130SILT; Manufacturer: Texas Instruments; SymbolCreator: Altium; SizeArea_mm2: 12.25; SizeAreaWB_mm2: 20.25; SizeX_mm: 3.5; SizeZ_mm: 1.53; CompType: IC; U/M: EA
U40 = NFM31PC276B0J3L: FILTER LC HIGH FREQ 27uF 1206; Manufacturer: MuRata; SymbolCreator: Altium
U41 = TPS7A8400RGRR: High-Current (3 A), High-Accuracy (1%), Low-Noise (4.4 μVRMS), LDO Voltage Regulator, RGR0020A (VQFN-20); Alternate PartNumber: TPS7A8400RGRT; Manufacturer: Texas Instruments; SymbolCreator: a0411947; SizeArea_mm2: 12.25; SizeAreaWB_mm2: 20.25; SizeX_mm: 3.5; SizeZ_mm: 1; CompType: IC; U/M: EA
